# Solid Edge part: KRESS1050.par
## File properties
Author: f_grande
Template: Normal.par
Last saved by: f_grande
Revision: 1
Application: Solid Edge
Precisione: 0,990
Tipo di contenuto documento: 0
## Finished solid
Body 1: solid body, 1 face, 0 edges, 0 vertices.
  Faces by surface: none 1
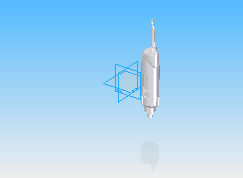
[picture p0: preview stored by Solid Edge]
